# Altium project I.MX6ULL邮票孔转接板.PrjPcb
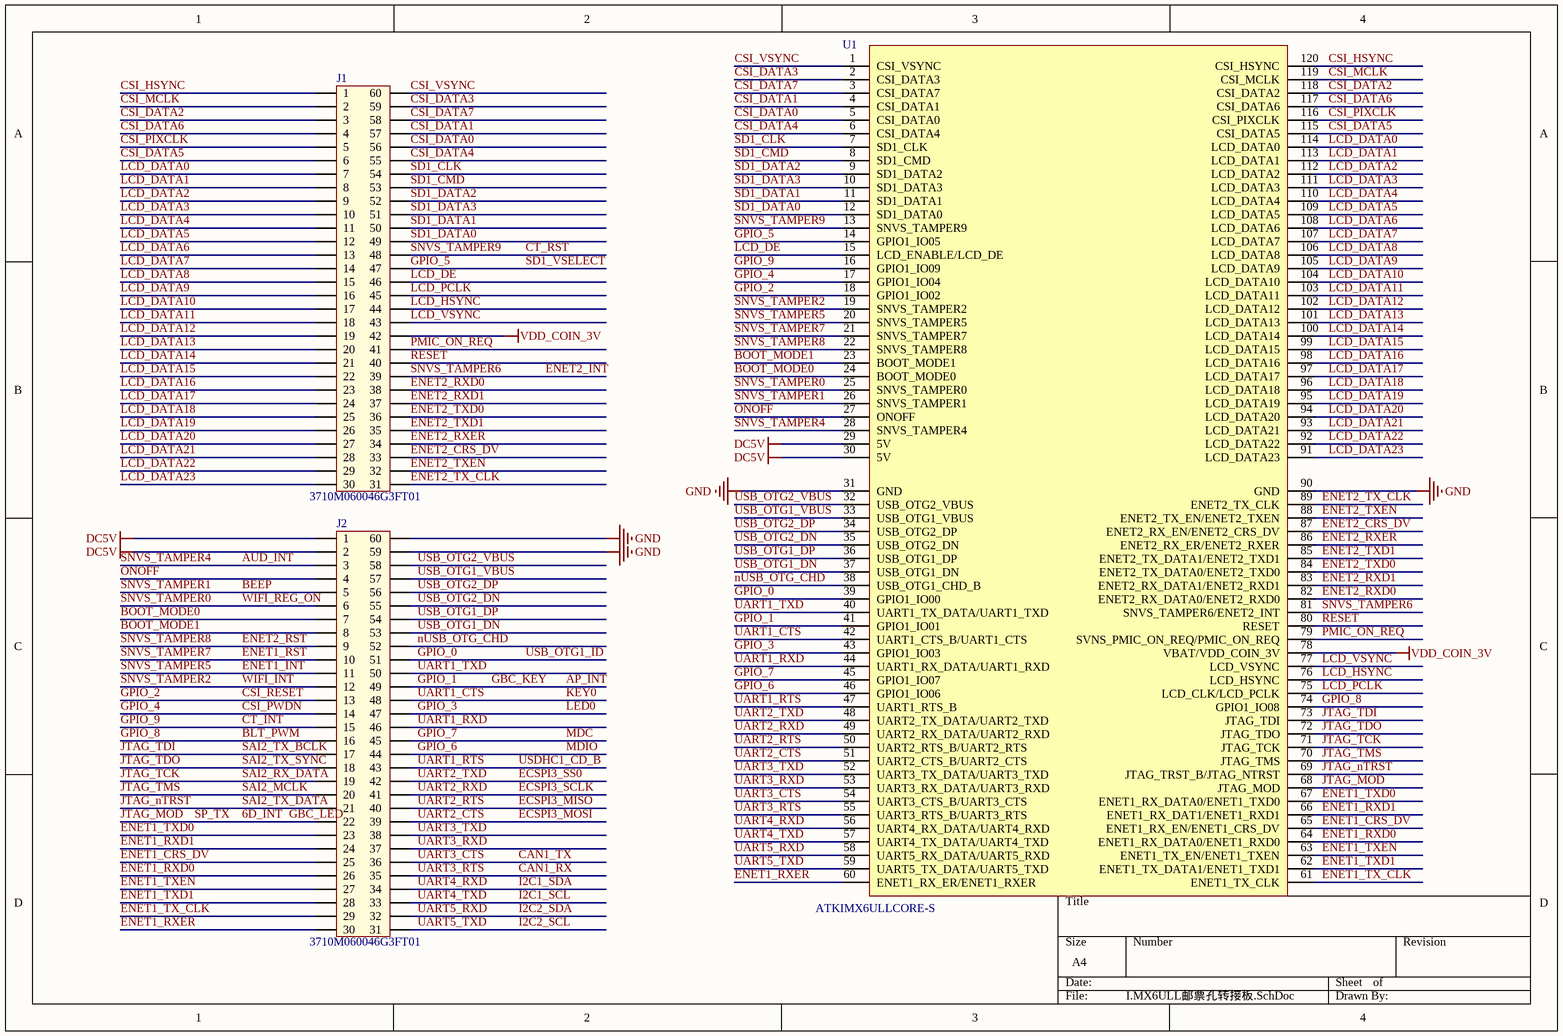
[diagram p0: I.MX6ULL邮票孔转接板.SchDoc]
1 sheet, 3 parts. Net scope: global (net labels, ports and power ports of the same name join across sheets).
Board file: I.MX6ULL邮票孔转接板.PcbDoc

## Sheet I.MX6ULL邮票孔转接板.SchDoc
size A4

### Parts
J1  3710M060046G3FT01  [3710F060046G3FT01]
J2  3710M060046G3FT01  [3710F060046G3FT01]
U1  ATKIMX6ULLCORE-S  [ATKIMX6ULLCORE-S]

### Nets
DC5V: J2.1 J2.2 U1.29(5V) U1.30(5V)
GND: J2.59 J2.60 U1.31(GND) U1.90(GND)
VDD_COIN_3V: J1.42 U1.78(VBAT/VDD_COIN_3V)
6D_INT: J2.22 U1.68(JTAG_MOD)  [also labelled GBC_LED, JTAG_MOD, SP_TX]
AP_INT: J2.49 U1.41(GPIO1_IO01)  [also labelled GBC_KEY, GPIO_1]
AUD_INT: J2.3 U1.28(SNVS_TAMPER4)  [also labelled SNVS_TAMPER4]
BEEP: J2.5 U1.26(SNVS_TAMPER1)  [also labelled SNVS_TAMPER1]
BLT_PWM: J2.16 U1.74(GPIO1_IO08)  [also labelled GPIO_8]
BOOT_MODE0: J2.7 U1.24(BOOT_MODE0)
BOOT_MODE1: J2.8 U1.23(BOOT_MODE1)
CAN1_RX: J2.35 U1.55(UART3_RTS_B/UART3_RTS)  [also labelled UART3_RTS]
CAN1_TX: J2.36 U1.54(UART3_CTS_B/UART3_CTS)  [also labelled UART3_CTS]
CSI_DATA0: J1.56 U1.5(CSI_DATA0)
CSI_DATA1: J1.57 U1.4(CSI_DATA1)
CSI_DATA2: J1.3 U1.118(CSI_DATA2)
CSI_DATA3: J1.59 U1.2(CSI_DATA3)
CSI_DATA4: J1.55 U1.6(CSI_DATA4)
CSI_DATA5: J1.6 U1.115(CSI_DATA5)
CSI_DATA6: J1.4 U1.117(CSI_DATA6)
CSI_DATA7: J1.58 U1.3(CSI_DATA7)
CSI_HSYNC: J1.1 U1.120(CSI_HSYNC)
CSI_MCLK: J1.2 U1.119(CSI_MCLK)
CSI_PIXCLK: J1.5 U1.116(CSI_PIXCLK)
CSI_PWDN: J2.14 U1.17(GPIO1_IO04)  [also labelled GPIO_4]
CSI_RESET: J2.13 U1.18(GPIO1_IO02)  [also labelled GPIO_2]
CSI_VSYNC: J1.60 U1.1(CSI_VSYNC)
CT_INT: J2.15 U1.16(GPIO1_IO09)  [also labelled GPIO_9]
CT_RST: J1.48 U1.13(SNVS_TAMPER9)  [also labelled SNVS_TAMPER9]
ECSPI3_MISO: J2.40 U1.50(UART2_RTS_B/UART2_RTS)  [also labelled UART2_RTS]
ECSPI3_MOSI: J2.39 U1.51(UART2_CTS_B/UART2_CTS)  [also labelled UART2_CTS]
ECSPI3_SCLK: J2.41 U1.49(UART2_RX_DATA/UART2_RXD)  [also labelled UART2_RXD]
ECSPI3_SS0: J2.42 U1.48(UART2_TX_DATA/UART2_TXD)  [also labelled UART2_TXD]
ENET1_CRS_DV: J2.25 U1.65(ENET1_RX_EN/ENET1_CRS_DV)
ENET1_INT: J2.11 U1.20(SNVS_TAMPER5)  [also labelled SNVS_TAMPER5]
ENET1_RST: J2.10 U1.21(SNVS_TAMPER7)  [also labelled SNVS_TAMPER7]
ENET1_RXD0: J2.26 U1.64(ENET1_RX_DATA0/ENET1_RXD0)
ENET1_RXD1: J2.24 U1.66(ENET1_RX_DAT1/ENET1_RXD1)
ENET1_RXER: J2.30 U1.60(ENET1_RX_ER/ENET1_RXER)
ENET1_TX_CLK: J2.29 U1.61(ENET1_TX_CLK)
ENET1_TXD0: J2.23 U1.67(ENET1_RX_DATA0/ENET1_TXD0)
ENET1_TXD1: J2.28 U1.62(ENET1_TX_DATA1/ENET1_TXD1)
ENET1_TXEN: J2.27 U1.63(ENET1_TX_EN/ENET1_TXEN)
ENET2_CRS_DV: J1.33 U1.87(ENET2_RX_EN/ENET2_CRS_DV)
ENET2_INT: J1.39 U1.81(SNVS_TAMPER6/ENET2_INT)  [also labelled SNVS_TAMPER6]
ENET2_RST: J2.9 U1.22(SNVS_TAMPER8)  [also labelled SNVS_TAMPER8]
ENET2_RXD0: J1.38 U1.82(ENET2_RX_DATA0/ENET2_RXD0)
ENET2_RXD1: J1.37 U1.83(ENET2_RX_DATA1/ENET2_RXD1)
ENET2_RXER: J1.34 U1.86(ENET2_RX_ER/ENET2_RXER)
ENET2_TX_CLK: J1.31 U1.89(ENET2_TX_CLK)
ENET2_TXD0: J1.36 U1.84(ENET2_TX_DATA0/ENET2_TXD0)
ENET2_TXD1: J1.35 U1.85(ENET2_TX_DATA1/ENET2_TXD1)
ENET2_TXEN: J1.32 U1.88(ENET2_TX_EN/ENET2_TXEN)
GPIO_0: J2.51 U1.39(GPIO1_IO00)  [also labelled USB_OTG1_ID]
GPIO_3: J2.47 U1.43(GPIO1_IO03)  [also labelled LED0]
GPIO_5: J1.47 U1.14(GPIO1_IO05)  [also labelled SD1_VSELECT]
GPIO_6: J2.44 U1.46(GPIO1_IO06)  [also labelled MDIO]
GPIO_7: J2.45 U1.45(GPIO1_IO07)  [also labelled MDC]
I2C1_SCL: J2.33 U1.57(UART4_TX_DATA/UART4_TXD)  [also labelled UART4_TXD]
I2C1_SDA: J2.34 U1.56(UART4_RX_DATA/UART4_RXD)  [also labelled UART4_RXD]
I2C2_SCL: J2.31 U1.59(UART5_TX_DATA/UART5_TXD)  [also labelled UART5_TXD]
I2C2_SDA: J2.32 U1.58(UART5_RX_DATA/UART5_RXD)  [also labelled UART5_RXD]
JTAG_nTRST: J2.21 U1.69(JTAG_TRST_B/JTAG_NTRST)  [also labelled SAI2_TX_DATA]
JTAG_TCK: J2.19 U1.71(JTAG_TCK)  [also labelled SAI2_RX_DATA]
JTAG_TDI: J2.17 U1.73(JTAG_TDI)  [also labelled SAI2_TX_BCLK]
JTAG_TDO: J2.18 U1.72(JTAG_TDO)  [also labelled SAI2_TX_SYNC]
JTAG_TMS: J2.20 U1.70(JTAG_TMS)  [also labelled SAI2_MCLK]
KEY0: J2.48 U1.42(UART1_CTS_B/UART1_CTS)  [also labelled UART1_CTS]
LCD_DATA0: J1.7 U1.114(LCD_DATA0)
LCD_DATA1: J1.8 U1.113(LCD_DATA1)
LCD_DATA2: J1.9 U1.112(LCD_DATA2)
LCD_DATA3: J1.10 U1.111(LCD_DATA3)
LCD_DATA4: J1.11 U1.110(LCD_DATA4)
LCD_DATA5: J1.12 U1.109(LCD_DATA5)
LCD_DATA6: J1.13 U1.108(LCD_DATA6)
LCD_DATA7: J1.14 U1.107(LCD_DATA7)
LCD_DATA8: J1.15 U1.106(LCD_DATA8)
LCD_DATA9: J1.16 U1.105(LCD_DATA9)
LCD_DATA10: J1.17 U1.104(LCD_DATA10)
LCD_DATA11: J1.18 U1.103(LCD_DATA11)
LCD_DATA12: J1.19 U1.102(LCD_DATA12)
LCD_DATA13: J1.20 U1.101(LCD_DATA13)
LCD_DATA14: J1.21 U1.100(LCD_DATA14)
LCD_DATA15: J1.22 U1.99(LCD_DATA15)
LCD_DATA16: J1.23 U1.98(LCD_DATA16)
LCD_DATA17: J1.24 U1.97(LCD_DATA17)
LCD_DATA18: J1.25 U1.96(LCD_DATA18)
LCD_DATA19: J1.26 U1.95(LCD_DATA19)
LCD_DATA20: J1.27 U1.94(LCD_DATA20)
LCD_DATA21: J1.28 U1.93(LCD_DATA21)
LCD_DATA22: J1.29 U1.92(LCD_DATA22)
LCD_DATA23: J1.30 U1.91(LCD_DATA23)
LCD_DE: J1.46 U1.15(LCD_ENABLE/LCD_DE)
LCD_HSYNC: J1.44 U1.76(LCD_HSYNC)
LCD_PCLK: J1.45 U1.75(LCD_CLK/LCD_PCLK)
LCD_VSYNC: J1.43 U1.77(LCD_VSYNC)
nUSB_OTG_CHD: J2.52 U1.38(USB_OTG1_CHD_B)
ONOFF: J2.4 U1.27(ONOFF)
PMIC_ON_REQ: J1.41 U1.79(SVNS_PMIC_ON_REQ/PMIC_ON_REQ)
RESET: J1.40 U1.80(RESET)
SD1_CLK: J1.54 U1.7(SD1_CLK)
SD1_CMD: J1.53 U1.8(SD1_CMD)
SD1_DATA0: J1.49 U1.12(SD1_DATA0)
SD1_DATA1: J1.50 U1.11(SD1_DATA1)
SD1_DATA2: J1.52 U1.9(SD1_DATA2)
SD1_DATA3: J1.51 U1.10(SD1_DATA3)
SNVS_TAMPER0: J2.6 U1.25(SNVS_TAMPER0)  [also labelled WIFI_REG_ON]
SNVS_TAMPER2: J2.12 U1.19(SNVS_TAMPER2)  [also labelled WIFI_INT]
UART1_RTS: J2.43 U1.47(UART1_RTS_B)  [also labelled USDHC1_CD_B]
UART1_RXD: J2.46 U1.44(UART1_RX_DATA/UART1_RXD)
UART1_TXD: J2.50 U1.40(UART1_TX_DATA/UART1_TXD)
UART3_RXD: J2.37 U1.53(UART3_RX_DATA/UART3_RXD)
UART3_TXD: J2.38 U1.52(UART3_TX_DATA/UART3_TXD)
USB_OTG1_DN: J2.53 U1.37(USB_OTG1_DN)
USB_OTG1_DP: J2.54 U1.36(USB_OTG1_DP)
USB_OTG1_VBUS: J2.57 U1.33(USB_OTG1_VBUS)
USB_OTG2_DN: J2.55 U1.35(USB_OTG2_DN)
USB_OTG2_DP: J2.56 U1.34(USB_OTG2_DP)
USB_OTG2_VBUS: J2.58 U1.32(USB_OTG2_VBUS)

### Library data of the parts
J1 J2 = 3710F: 3710F060046G3FT01
U1 = ATKIMX6ULLCORE-S: 正点原子I.MX6ULL邮票孔核心板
